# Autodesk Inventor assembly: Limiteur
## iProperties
Created: 2002-05
Part Number: Limiteur
Document SubType Name: Assemblage
Designer: Flavien MARTY
Control State: 0
Master: False
Checked Out: False
Shininess: 41.0
Length Units: 11269
Angle Units: 11279
Time Units: 11290
Mass Units: 11283
Length Display Precision: 3
Angle Display Precision: 2
Compacted: True
Density: 0.0
Volumn: 0.0
Area: 0.0
PropertySet Name: Model Information
Author: Flavien MARTY
